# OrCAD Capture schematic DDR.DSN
size A3
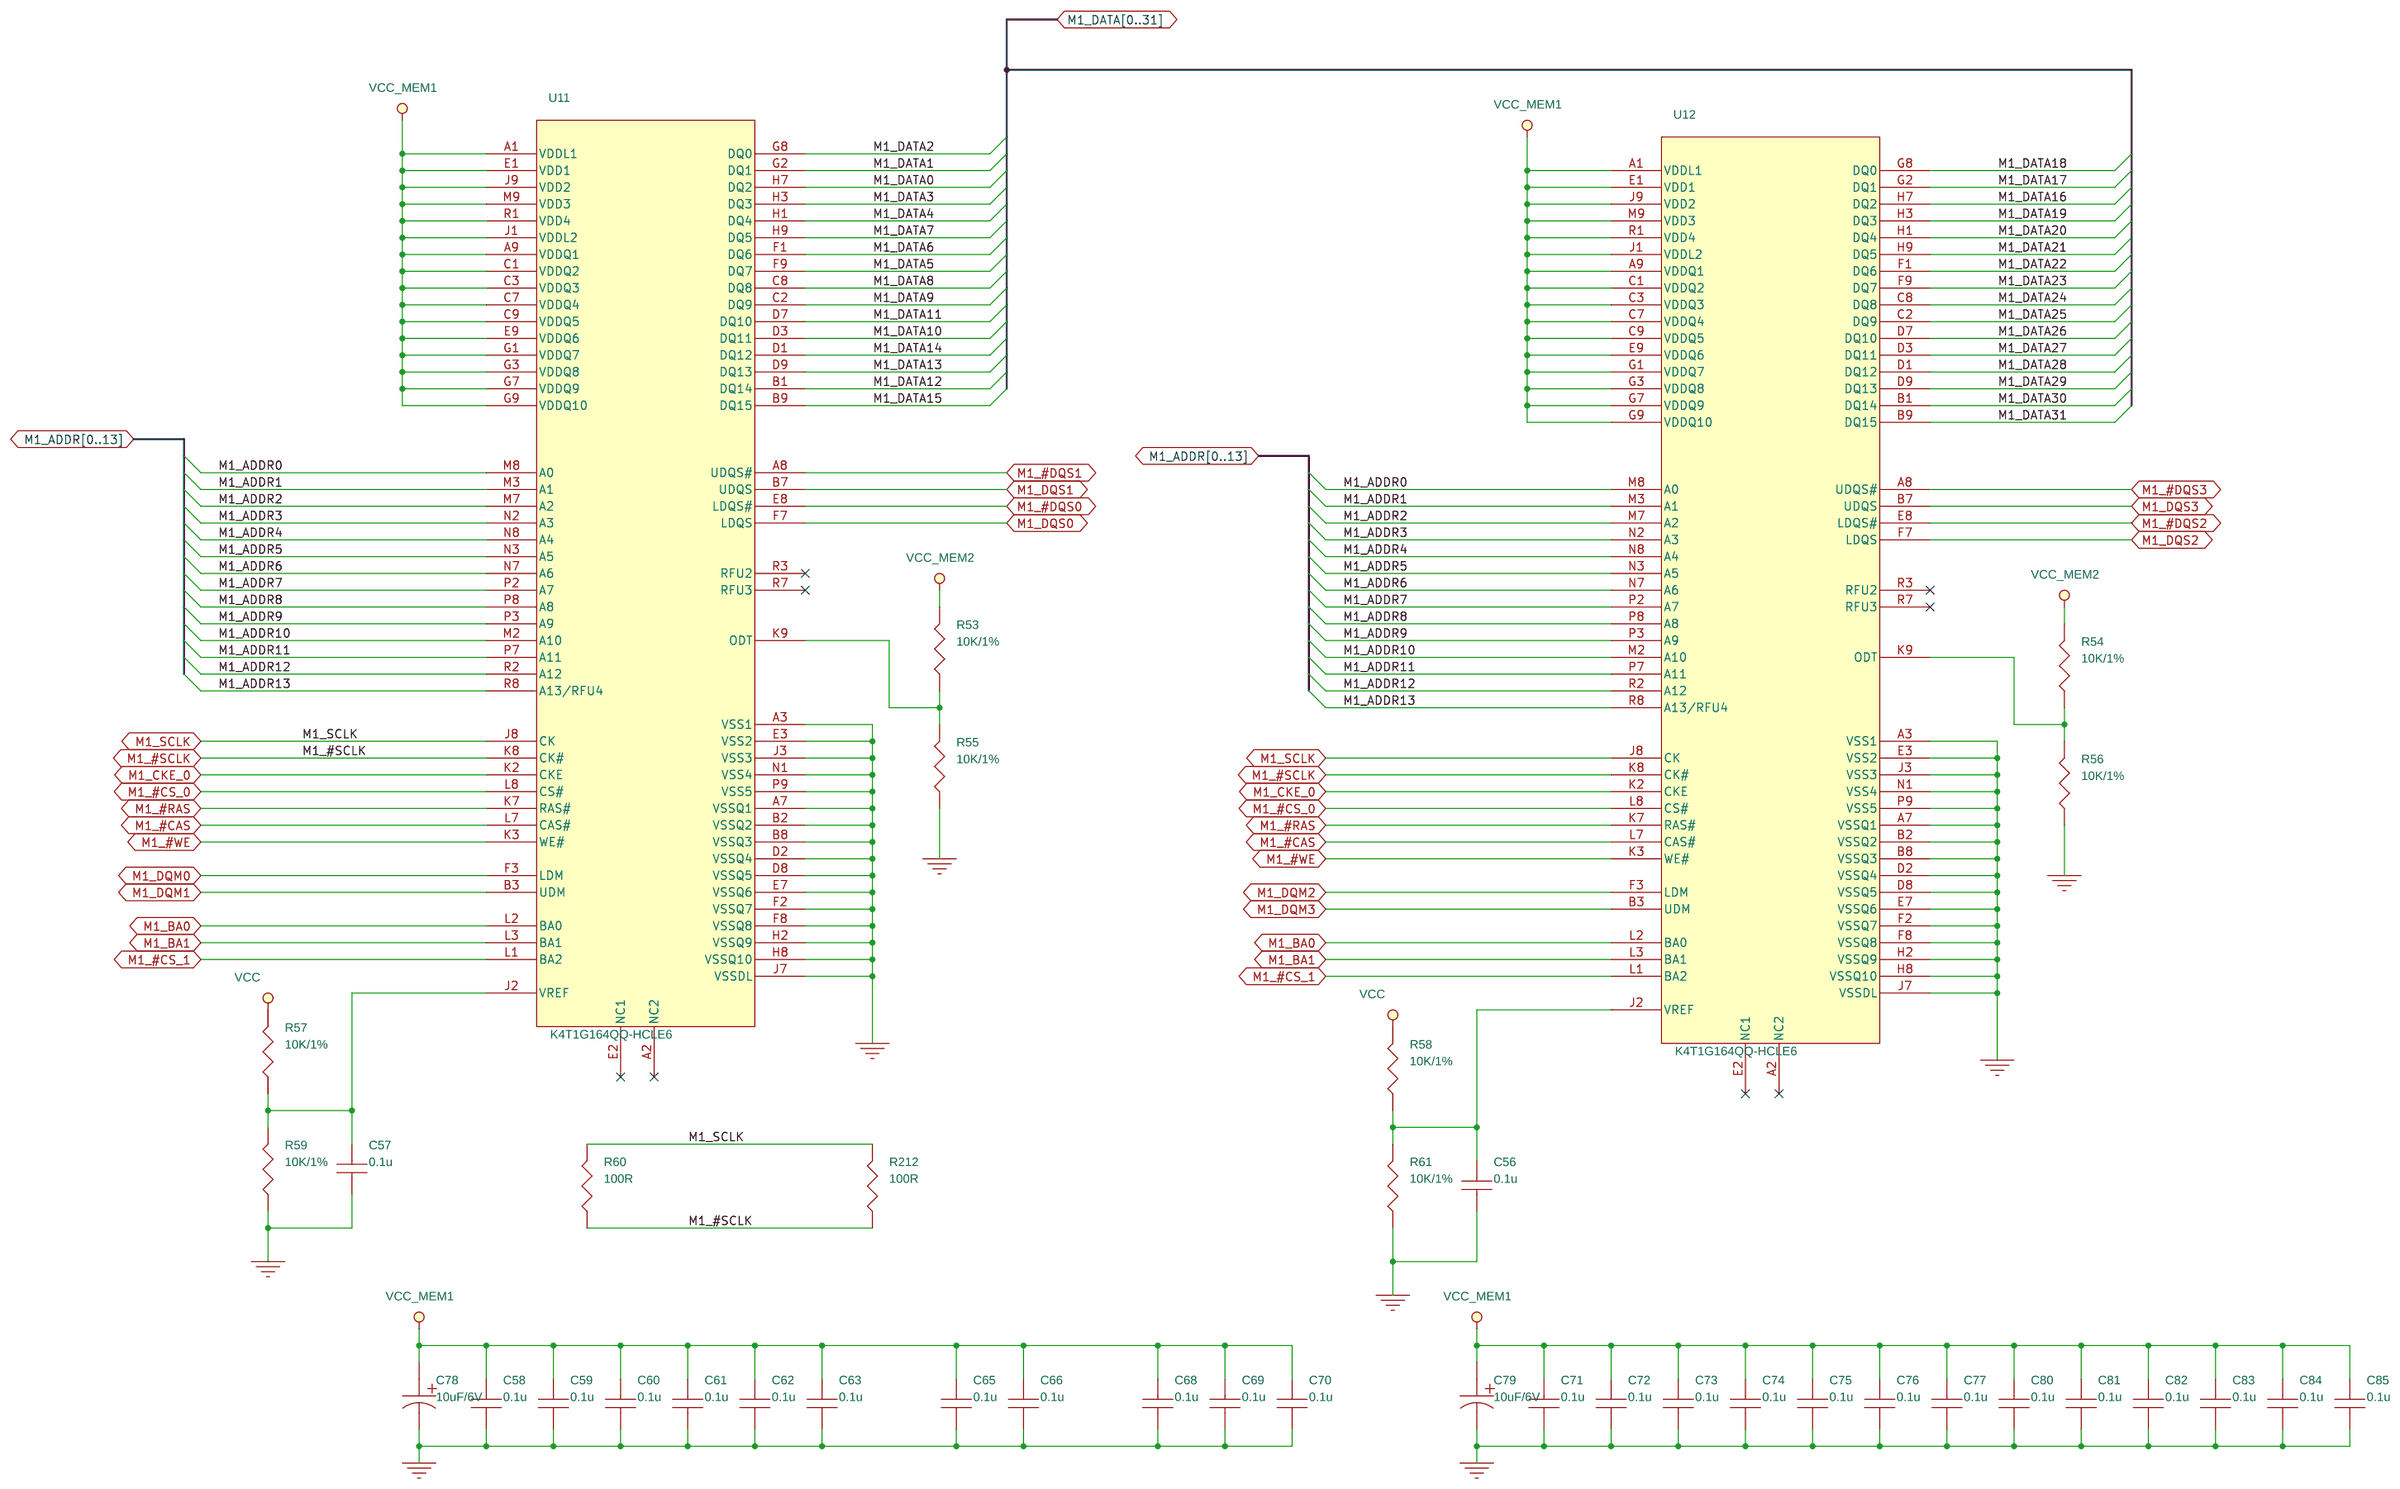
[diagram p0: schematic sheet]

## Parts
C56  0.1u  [cap0402]
C57  0.1u  [cap0402]
C58  0.1u  [cap0402]
C59  0.1u  [cap0402]
C60  0.1u  [cap0402]
C61  0.1u  [cap0402]
C62  0.1u  [cap0402]
C63  0.1u  [cap0402]
C65  0.1u  [cap0402]
C66  0.1u  [cap0402]
C68  0.1u  [cap0402]
C69  0.1u  [cap0402]
C70  0.1u  [cap0402]
C71  0.1u  [cap0402]
C72  0.1u  [cap0402]
C73  0.1u  [cap0402]
C74  0.1u  [cap0402]
C75  0.1u  [cap0402]
C76  0.1u  [cap0402]
C77  0.1u  [cap0402]
C78  10uF/6V  [cap3216]
C79  10uF/6V  [cap3216]
C80  0.1u  [cap0402]
C81  0.1u  [cap0402]
C82  0.1u  [cap0402]
C83  0.1u  [cap0402]
C84  0.1u  [cap0402]
C85  0.1u  [cap0402]
R53  10K/1%  [res0402]
R54  10K/1%  [res0402]
R55  10K/1%  [res0402]
R56  10K/1%  [res0402]
R57  10K/1%  [res0402]
R58  10K/1%  [res0402]
R59  10K/1%  [res0402]
R60  100R  [res0402]
R61  10K/1%  [res0402]
R212  100R  [res0402]
U11  K4T1G164QQ-HCLE6  [bga84pind0_80pad0_35]
U12  K4T1G164QQ-HCLE6  [bga84pind0_80pad0_35]

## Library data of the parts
C56-C63 C65 C66 C68-C77 C80-C85 = CAP_NP: MEM DDR: 5
C78 C79 = CAP_POL: MEM DDR: 5
R53-R61 R212 = RESISTOR: MEM DDR: 5
U11 U12 = K4T1G164QQ-HCLE6_0: MEM DDR: 5

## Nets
GND: C56.2 C57.2 C58.2 C59.2 C60.2 C61.2 C62.2 C63.2 C65.2 C66.2 C68.2 C69.2 C70.2 C71.2 C72.2 C73.2 C74.2 C75.2 C76.2 C77.2 C78.2 C79.2 C80.2 C81.2 C82.2 C83.2 C84.2 C85.2 R55.1 R56.1 R59.1 R61.1 U11.A3(VSS1) U11.A7(VSSQ1) U11.B2(VSSQ2) U11.B8(VSSQ3) U11.D2(VSSQ4) U11.D8(VSSQ5) U11.E3(VSS2) U11.E7(VSSQ6) U11.F2(VSSQ7) U11.F8(VSSQ8) U11.H2(VSSQ9) U11.H8(VSSQ10) U11.J3(VSS3) U11.J7(VSSDL) U11.N1(VSS4) U11.P9(VSS5) U12.A3(VSS1) U12.A7(VSSQ1) U12.B2(VSSQ2) U12.B8(VSSQ3) U12.D2(VSSQ4) U12.D8(VSSQ5) U12.E3(VSS2) U12.E7(VSSQ6) U12.F2(VSSQ7) U12.F8(VSSQ8) U12.H2(VSSQ9) U12.H8(VSSQ10) U12.J3(VSS3) U12.J7(VSSDL) U12.N1(VSS4) U12.P9(VSS5)
VCC_MEM1: C58.1 C59.1 C60.1 C61.1 C62.1 C63.1 C65.1 C66.1 C68.1 C69.1 C70.1 C71.1 C72.1 C73.1 C74.1 C75.1 C76.1 C77.1 C78.1 C79.1 C80.1 C81.1 C82.1 C83.1 C84.1 C85.1 R57.2 R58.2 U11.A1(VDDL1) U11.A9(VDDQ1) U11.C1(VDDQ2) U11.C3(VDDQ3) U11.C7(VDDQ4) U11.C9(VDDQ5) U11.E1(VDD1) U11.E9(VDDQ6) U11.G1(VDDQ7) U11.G3(VDDQ8) U11.G7(VDDQ9) U11.G9(VDDQ10) U11.J1(VDDL2) U11.J9(VDD2) U11.M9(VDD3) U11.R1(VDD4) U12.A1(VDDL1) U12.A9(VDDQ1) U12.C1(VDDQ2) U12.C3(VDDQ3) U12.C7(VDDQ4) U12.C9(VDDQ5) U12.E1(VDD1) U12.E9(VDDQ6) U12.G1(VDDQ7) U12.G3(VDDQ8) U12.G7(VDDQ9) U12.G9(VDDQ10) U12.J1(VDDL2) U12.J9(VDD2) U12.M9(VDD3) U12.R1(VDD4)
VCC_MEM2: R53.2 R54.2
M1_#CAS: U11.L7(CAS#) U12.L7(CAS#)
M1_#CS_0: U11.L8(CS#) U12.L8(CS#)
M1_#CS_1: U11.L1(BA2) U12.L1(BA2)
M1_#DQS0: U11.E8(LDQS#)
M1_#DQS1: U11.A8(UDQS#)
M1_#DQS2: U12.E8(LDQS#)
M1_#DQS3: U12.A8(UDQS#)
M1_#RAS: U11.K7(RAS#) U12.K7(RAS#)
M1_#SCLK: R60.1 R212.1 U11.K8(CK#) U12.K8(CK#)
M1_#WE: U11.K3(WE#) U12.K3(WE#)
M1_ADDR0: U11.M8(A0) U12.M8(A0)
M1_ADDR1: U11.M3(A1) U12.M3(A1)
M1_ADDR2: U11.M7(A2) U12.M7(A2)
M1_ADDR3: U11.N2(A3) U12.N2(A3)
M1_ADDR4: U11.N8(A4) U12.N8(A4)
M1_ADDR5: U11.N3(A5) U12.N3(A5)
M1_ADDR6: U11.N7(A6) U12.N7(A6)
M1_ADDR7: U11.P2(A7) U12.P2(A7)
M1_ADDR8: U11.P8(A8) U12.P8(A8)
M1_ADDR9: U11.P3(A9) U12.P3(A9)
M1_ADDR10: U11.M2(A10) U12.M2(A10)
M1_ADDR11: U11.P7(A11) U12.P7(A11)
M1_ADDR12: U11.R2(A12) U12.R2(A12)
M1_ADDR13: U11.R8(A13/RFU4) U12.R8(A13/RFU4)
M1_BA0: U11.L2(BA0) U12.L2(BA0)
M1_BA1: U11.L3(BA1) U12.L3(BA1)
M1_CKE_0: U11.K2(CKE) U12.K2(CKE)
M1_DATA0: U11.H7(DQ2)
M1_DATA1: U11.G2(DQ1)
M1_DATA2: U11.G8(DQ0)
M1_DATA3: U11.H3(DQ3)
M1_DATA4: U11.H1(DQ4)
M1_DATA5: U11.F9(DQ7)
M1_DATA6: U11.F1(DQ6)
M1_DATA7: U11.H9(DQ5)
M1_DATA8: U11.C8(DQ8)
M1_DATA9: U11.C2(DQ9)
M1_DATA10: U11.D3(DQ11)
M1_DATA11: U11.D7(DQ10)
M1_DATA12: U11.B1(DQ14)
M1_DATA13: U11.D9(DQ13)
M1_DATA14: U11.D1(DQ12)
M1_DATA15: U11.B9(DQ15)
M1_DATA16: U12.H7(DQ2)
M1_DATA17: U12.G2(DQ1)
M1_DATA18: U12.G8(DQ0)
M1_DATA19: U12.H3(DQ3)
M1_DATA20: U12.H1(DQ4)
M1_DATA21: U12.H9(DQ5)
M1_DATA22: U12.F1(DQ6)
M1_DATA23: U12.F9(DQ7)
M1_DATA24: U12.C8(DQ8)
M1_DATA25: U12.C2(DQ9)
M1_DATA26: U12.D7(DQ10)
M1_DATA27: U12.D3(DQ11)
M1_DATA28: U12.D1(DQ12)
M1_DATA29: U12.D9(DQ13)
M1_DATA30: U12.B1(DQ14)
M1_DATA31: U12.B9(DQ15)
M1_DQM0: U11.F3(LDM)
M1_DQM1: U11.B3(UDM)
M1_DQM2: U12.F3(LDM)
M1_DQM3: U12.B3(UDM)
M1_DQS0: U11.F7(LDQS)
M1_DQS1: U11.B7(UDQS)
M1_DQS2: U12.F7(LDQS)
M1_DQS3: U12.B7(UDQS)
M1_SCLK: R60.2 R212.2 U11.J8(CK) U12.J8(CK)
N15112373: C57.1 R57.1 R59.2 U11.J2(VREF)
N15112945: C56.1 R58.1 R61.2 U12.J2(VREF)
N15113093: R53.1 R55.2 U11.K9(ODT)
N15113193: R54.1 R56.2 U12.K9(ODT)

Not connected (* = marked no-connect by the designer): U11 A2(NC2)* E2(NC1)* R3(RFU2)* R7(RFU3)*; U12 A2(NC2)* E2(NC1)* R3(RFU2)* R7(RFU3)*
